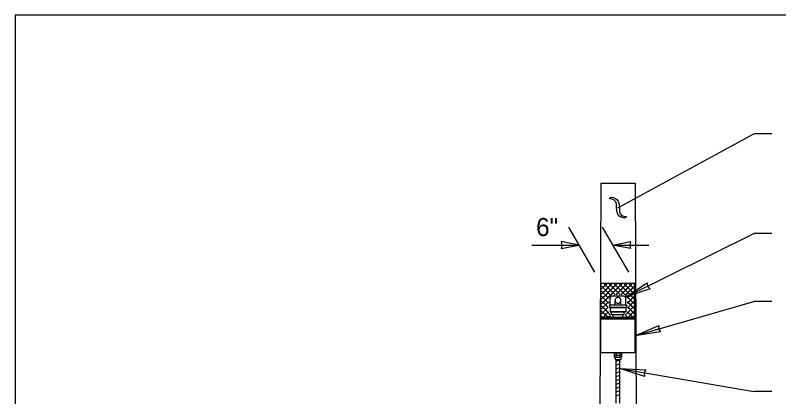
# Model space of a CAD drawing. Extents: x 99862 to 103151, y 100000 to 105076.
# Drawn here: x 99862 to 100537, y 101738 to 102076 of the extents above; entities that cross this region are included whole.
import ezdxf

# ---------------------------------------------------------------- set-up
doc = ezdxf.new("R2010")
doc.units = 0
for name, color, linetype in [('Level 1', 7, 'Continuous'), ('Level 15', 7, 'Continuous'), ('Level 20', 7, 'Continuous'), ('Level 40', 7, 'Continuous')]:
    doc.layers.add(name, color=color, linetype=linetype)

msp = doc.modelspace()

# ---------------------------------------------------------------- linework, layer by layer
at = {"layer": 'Level 1'}
for p, q in [((100379.91, 101927.16), (100378.26, 101563.05)), ((100379.91, 101927.16), (100410.16, 101927.16)), ((100410.16, 101927.16), (100411.8, 101563.05)), ((100410.03, 101838.33), (100380.03, 101838.33)), ((100380.03, 101808.33), (100380.03, 101838.33)), ((100380.84, 101838.33), (100380.03, 101837.52)), ((100383.98, 101837.05), (100382.71, 101838.33)), ((100385.26, 101838.33), (100383.98, 101837.05)), ((100388.4, 101837.05), (100387.13, 101838.33)), ((100389.68, 101838.33), (100388.4, 101837.05)), ((100392.82, 101837.05), (100391.55, 101838.33)), ((100394.1, 101838.33), (100392.82, 101837.05)), ((100397.24, 101837.05), (100395.97, 101838.33)), ((100398.52, 101838.33), (100397.24, 101837.05)), ((100401.66, 101837.05), (100400.39, 101838.33)), ((100402.93, 101838.33), (100401.66, 101837.05)), ((100406.08, 101837.05), (100404.81, 101838.33)), ((100407.35, 101838.33), (100406.08, 101837.05)), ((100410.03, 101837.52), (100409.23, 101838.33)), ((100410.03, 101808.33), (100410.03, 101838.33)), ((100380.03, 101836.59), (100381.77, 101834.84)), ((100381.77, 101834.84), (100380.03, 101833.1)), ((100380.03, 101832.17), (100381.77, 101830.42)), ((100381.77, 101834.84), (100383.98, 101837.05)), ((100383.98, 101832.63), (100381.77, 101834.84)), ((100381.77, 101830.42), (100383.98, 101832.63)), ((100383.98, 101837.05), (100386.19, 101834.84)), ((100386.19, 101834.84), (100383.98, 101832.63)), ((100383.98, 101832.63), (100386.19, 101830.42)), ((100386.19, 101834.84), (100388.4, 101837.05)), ((100388.4, 101832.63), (100386.19, 101834.84)), ((100386.19, 101830.42), (100388.4, 101832.63)), ((100388.4, 101837.05), (100390.61, 101834.84)), ((100390.61, 101834.84), (100388.4, 101832.63)), ((100388.4, 101832.63), (100390.61, 101830.42)), ((100390.61, 101834.84), (100392.82, 101837.05)), ((100392.82, 101832.63), (100390.61, 101834.84)), ((100390.61, 101830.42), (100392.82, 101832.63)), ((100392.82, 101837.05), (100395.03, 101834.84)), ((100395.03, 101834.84), (100392.82, 101832.63)), ((100392.82, 101832.63), (100395.03, 101830.42)), ((100395.03, 101834.84), (100397.24, 101837.05)), ((100397.24, 101832.63), (100395.03, 101834.84)), ((100395.03, 101830.42), (100397.24, 101832.63)), ((100397.24, 101837.05), (100399.45, 101834.84)), ((100399.45, 101834.84), (100397.24, 101832.63)), ((100397.24, 101832.63), (100399.45, 101830.42)), ((100399.45, 101834.84), (100401.66, 101837.05)), ((100401.66, 101832.63), (100399.45, 101834.84)), ((100399.45, 101830.42), (100401.66, 101832.63)), ((100401.66, 101837.05), (100403.87, 101834.84)), ((100403.87, 101834.84), (100401.66, 101832.63)), ((100401.66, 101832.63), (100403.87, 101830.42)), ((100403.87, 101834.84), (100406.08, 101837.05)), ((100406.08, 101832.63), (100403.87, 101834.84)), ((100403.87, 101830.42), (100406.08, 101832.63)), ((100406.08, 101837.05), (100408.29, 101834.84)), ((100408.29, 101834.84), (100406.08, 101832.63)), ((100406.08, 101832.63), (100408.29, 101830.42)), ((100408.29, 101834.84), (100410.03, 101836.58)), ((100410.03, 101833.1), (100408.29, 101834.84)), ((100408.29, 101830.42), (100410.03, 101832.17)), ((100381.77, 101830.42), (100380.03, 101828.68)), ((100380.03, 101827.75), (100381.77, 101826)), ((100381.77, 101826), (100380.03, 101824.26)), ((100383.98, 101828.21), (100381.77, 101830.42)), ((100381.77, 101826), (100383.98, 101828.21)), ((100383.98, 101823.79), (100381.77, 101826)), ((100386.19, 101830.42), (100383.98, 101828.21)), ((100383.98, 101828.21), (100386.19, 101826)), ((100386.19, 101826), (100383.98, 101823.79)), ((100388.4, 101828.21), (100386.19, 101830.42)), ((100386.19, 101826), (100388.4, 101828.21)), ((100386.91, 101825.29), (100386.19, 101826)), ((100388.16, 101819.66), (100388.16, 101825.49)), ((100390.61, 101830.42), (100388.4, 101828.21)), ((100388.4, 101828.21), (100388.51, 101828.1)), ((100400.24, 101827.16), (100389.82, 101827.16)), ((100392.62, 101828.41), (100390.61, 101830.42)), ((100395.03, 101830.42), (100393.02, 101828.41)), ((100397.04, 101828.41), (100395.03, 101830.42)), ((100399.45, 101830.42), (100397.44, 101828.41)), ((100401.66, 101828.21), (100399.45, 101830.42)), ((100401.55, 101828.1), (100401.66, 101828.21)), ((100403.87, 101830.42), (100401.66, 101828.21)), ((100401.66, 101828.21), (100403.87, 101826)), ((100401.91, 101819.66), (100401.91, 101825.49)), ((100403.87, 101826), (100403.16, 101825.29)), ((100406.08, 101828.21), (100403.87, 101830.42)), ((100403.87, 101826), (100406.08, 101828.21)), ((100406.08, 101823.79), (100403.87, 101826)), ((100408.29, 101830.42), (100406.08, 101828.21)), ((100406.08, 101828.21), (100408.29, 101826)), ((100408.29, 101826), (100406.08, 101823.79)), ((100410.03, 101828.68), (100408.29, 101830.42)), ((100408.29, 101826), (100410.03, 101827.75)), ((100410.03, 101824.26), (100408.29, 101826)), ((100380.03, 101823.33), (100381.77, 101821.59)), ((100381.77, 101821.59), (100380.03, 101819.84)), ((100380.03, 101818.91), (100381.77, 101817.17)), ((100381.77, 101821.59), (100383.98, 101823.79)), ((100383.98, 101819.38), (100381.77, 101821.59)), ((100381.77, 101817.17), (100383.98, 101819.38)), ((100383.98, 101823.79), (100386.19, 101821.59)), ((100386.19, 101821.59), (100383.98, 101819.38)), ((100383.98, 101819.38), (100386.19, 101817.17)), ((100386.19, 101821.59), (100386.91, 101822.3)), ((100386.87, 101820.91), (100386.19, 101821.59)), ((100388.16, 101819.66), (100387.53, 101819.66)), ((100387.53, 101819.66), (100387.53, 101817.16)), ((100388.16, 101819.66), (100401.91, 101819.66)), ((100392.53, 101819.66), (100392.53, 101823.49)), ((100397.53, 101819.66), (100397.53, 101823.49)), ((100401.91, 101819.66), (100402.53, 101819.66)), ((100402.53, 101819.66), (100402.53, 101817.16)), ((100403.16, 101822.3), (100403.87, 101821.59)), ((100403.87, 101821.59), (100403.2, 101820.91)), ((100403.87, 101821.59), (100406.08, 101823.79)), ((100406.08, 101819.38), (100403.87, 101821.59)), ((100403.87, 101817.17), (100406.08, 101819.38)), ((100406.08, 101823.79), (100408.29, 101821.59)), ((100408.29, 101821.59), (100406.08, 101819.38)), ((100406.08, 101819.38), (100408.29, 101817.17)), ((100408.29, 101821.59), (100410.03, 101823.33)), ((100410.03, 101819.84), (100408.29, 101821.59)), ((100408.29, 101817.17), (100410.03, 101818.91)), ((100381.77, 101817.17), (100380.03, 101815.42)), ((100380.03, 101814.49), (100381.77, 101812.75)), ((100381.77, 101812.75), (100380.03, 101811)), ((100383.98, 101814.96), (100381.77, 101817.17)), ((100381.77, 101812.75), (100383.98, 101814.96)), ((100383.98, 101810.54), (100381.77, 101812.75)), ((100386.19, 101817.17), (100383.98, 101814.96)), ((100383.98, 101814.96), (100386.19, 101812.75)), ((100386.19, 101812.75), (100383.98, 101810.54)), ((100386.19, 101817.17), (100386.28, 101817.25)), ((100386.28, 101817.08), (100386.19, 101817.17)), ((100386.19, 101812.75), (100386.91, 101813.46)), ((100388.25, 101810.69), (100386.19, 101812.75)), ((100402.53, 101817.16), (100387.53, 101817.16)), ((100388.16, 101817.16), (100401.91, 101817.16)), ((100388.16, 101817.16), (100388.16, 101813.41)), ((100388.16, 101813.72), (100401.91, 101813.72)), ((100388.16, 101813.41), (100401.91, 101813.41)), ((100389.41, 101811.22), (100389.41, 101813.41)), ((100389.72, 101810.91), (100400.34, 101810.91)), ((100390.66, 101808.41), (100390.66, 101810.91)), ((100399.41, 101808.41), (100399.41, 101810.91)), ((100400.66, 101811.22), (100400.66, 101813.41)), ((100403.87, 101812.75), (100401.81, 101810.69)), ((100401.91, 101817.16), (100401.91, 101813.41)), ((100403.16, 101813.46), (100403.87, 101812.75)), ((100403.78, 101817.25), (100403.87, 101817.17)), ((100403.87, 101817.17), (100403.78, 101817.08)), ((100406.08, 101814.96), (100403.87, 101817.17)), ((100403.87, 101812.75), (100406.08, 101814.96)), ((100406.08, 101810.54), (100403.87, 101812.75)), ((100408.29, 101817.17), (100406.08, 101814.96)), ((100406.08, 101814.96), (100408.29, 101812.75)), ((100408.29, 101812.75), (100406.08, 101810.54)), ((100410.03, 101815.42), (100408.29, 101817.17)), ((100408.29, 101812.75), (100410.03, 101814.49)), ((100410.03, 101811), (100408.29, 101812.75)), ((100380.03, 101810.07), (100381.77, 101808.33)), ((100410.03, 101808.33), (100380.03, 101808.33)), ((100380.03, 101807.79), (100380.03, 101808.27)), ((100410.03, 101808.27), (100380.03, 101808.27)), ((100410.03, 101807.79), (100380.03, 101807.79)), ((100380.03, 101807.16), (100410.03, 101807.16)), ((100380.03, 101777.16), (100380.03, 101807.16)), ((100381.77, 101808.33), (100383.98, 101810.54)), ((100383.98, 101810.54), (100386.19, 101808.33)), ((100386.19, 101808.33), (100388.35, 101810.48)), ((100391.91, 101807.16), (100398.16, 101807.16)), ((100401.72, 101810.48), (100403.87, 101808.33)), ((100403.87, 101808.33), (100406.08, 101810.54)), ((100406.08, 101810.54), (100408.29, 101808.33)), ((100408.29, 101808.33), (100410.03, 101810.07)), ((100410.03, 101807.79), (100410.03, 101808.27)), ((100410.03, 101807.16), (100410.03, 101777.16)), ((100410.03, 101777.16), (100380.03, 101777.16)), ((100391.81, 101777.16), (100391.81, 101773.13)), ((100391.81, 101777.16), (100398.26, 101777.16)), ((100393.34, 101777.16), (100393.34, 101773.13)), ((100396.56, 101777.16), (100396.56, 101773.13)), ((100398.26, 101777.16), (100398.26, 101773.13)), ((100391.81, 101775.15), (100398.26, 101775.15)), ((100391.81, 101773.13), (100398.26, 101773.13)), ((100392.53, 101773.13), (100392.53, 101771.19)), ((100392.53, 101771.19), (100397.53, 101771.19)), ((100393.43, 101732.7), (100393.43, 101771.19)), ((100393.43, 101769.73), (100396.63, 101770.9)), ((100396.63, 101732.7), (100396.63, 101771.19)), ((100397.53, 101773.13), (100397.53, 101771.19)), ((100393.43, 101766.34), (100396.63, 101767.5)), ((100393.43, 101762.94), (100396.63, 101764.11)), ((100393.43, 101759.55), (100396.63, 101760.71)), ((100393.43, 101756.15), (100396.63, 101757.32)), ((100393.43, 101752.75), (100396.63, 101753.92)), ((100393.43, 101749.36), (100396.63, 101750.53)), ((100393.43, 101745.96), (100396.63, 101747.13)), ((100393.43, 101742.57), (100396.63, 101743.73)), ((100393.43, 101739.17), (100396.63, 101740.34))]:
    msp.add_line(p, q, dxfattribs=at)
msp.add_lwpolyline([(99862, 99999.5), (103151, 99999.5), (103151, 102075.5), (99862, 102075.5)], close=True, dxfattribs=at)
for centre, radius, start, end in [((100389.82, 101825.49), 1.67, 90, 180), ((100395.03, 101823.49), 2.5, 359.99971, 180), ((100400.24, 101825.49), 1.67, 0, 90), ((100395.03, 101823.49), 2.5, 180, 0.00029), ((100389.72, 101811.22), 0.312, 180, 270), ((100400.34, 101811.22), 0.312, 270, 0), ((100391.91, 101808.41), 1.25, 180, 186.29473), ((100391.91, 101808.41), 1.25, 209.97018, 270), ((100398.16, 101808.41), 1.25, 270, 330.02982), ((100398.16, 101808.41), 1.25, 353.70527, 360)]:
    msp.add_arc(centre, radius, start, end, dxfattribs=at)
at = {"layer": 'Level 15'}
for p, q in [((100395.03, 101905.41), (100515.21, 101970.8)), ((100531.21, 101970.8), (100515.21, 101970.8)), ((100387.31, 101913.57), (100389.16, 101914.58)), ((100389.66, 101913), (100387.31, 101913.57)), ((100389.16, 101914.58), (100391.13, 101914.28)), ((100391.27, 101912.34), (100389.66, 101913)), ((100391.13, 101914.28), (100392.79, 101913.6)), ((100392.34, 101911.5), (100391.27, 101912.34)), ((100392.79, 101913.6), (100394.13, 101912.55)), ((100394.13, 101912.55), (100395.17, 101911.13)), ((100393.14, 101910.43), (100392.34, 101911.5)), ((100393.73, 101908.6), (100393.14, 101910.43)), ((100393.89, 101906.06), (100393.73, 101908.6)), ((100394.05, 101901.97), (100393.89, 101906.06)), ((100395.17, 101911.13), (100396.03, 101908.55)), ((100396.03, 101908.55), (100396.29, 101904.14)), ((100394.88, 101899.65), (100394.05, 101901.97)), ((100395.85, 101898.3), (100394.88, 101899.65)), ((100396.29, 101904.14), (100396.44, 101901.72)), ((100396.44, 101901.72), (100396.93, 101900.31)), ((100396.93, 101900.31), (100397.82, 101899.2)), ((100397.82, 101899.2), (100399.2, 101898.29)), ((100397.13, 101897.31), (100395.85, 101898.3)), ((100398.77, 101896.62), (100397.13, 101897.31)), ((100400.88, 101896.21), (100398.77, 101896.62)), ((100399.2, 101898.29), (100402.74, 101897.22)), ((100402.73, 101897.22), (100400.88, 101896.21)), ((100351.19, 101888.29), (100374.26, 101848.33)), ((100381.19, 101888.29), (100404.26, 101848.33)), ((100401.73, 101826.24), (100515.21, 101882.51)), ((100531.21, 101882.51), (100515.21, 101882.51)), ((100318.97, 101872.29), (100360.42, 101872.29)), ((100390.42, 101872.29), (100422.42, 101872.29)), ((100410.03, 101792.16), (100515.21, 101822.58)), ((100531.21, 101822.58), (100515.21, 101822.58)), ((100396.63, 101763.1), (100515.21, 101742.79)), ((100531.21, 101742.79), (100515.21, 101742.79))]:
    msp.add_line(p, q, dxfattribs=at)
for points in [[(100360.42, 101872.29), (100344.7, 101875.37), (100345.43, 101872.29), (100344.7, 101869.2)], [(100390.42, 101872.29), (100406.15, 101875.37), (100405.42, 101872.29), (100406.15, 101869.2)], [(100401.73, 101826.24), (100420.86, 101839.05), (100421.24, 101835.91), (100423.51, 101833.7)], [(100410.03, 101792.16), (100431.13, 101801.37), (100430.95, 101798.21), (100432.79, 101795.64)], [(100396.63, 101763.1), (100419.64, 101762.19), (100418.09, 101759.43), (100418.63, 101756.31)]]:
    msp.add_lwpolyline(points, close=True, dxfattribs=at)
at = {"layer": 'Level 40'}
for points in [[(100383.24, 101807.29), (100383.24, 101807.16), (100381.84, 101807.16), (100381.84, 101807.29)], [(100383.21, 101807.37), (100383.21, 101807.29), (100381.85, 101807.29), (100381.85, 101807.37)], [(100383.04, 101808.29), (100383.04, 101808.69), (100382.02, 101808.69), (100382.02, 101808.29)], [(100383.04, 101807.37), (100383.04, 101807.79), (100382.02, 101807.79), (100382.02, 101807.37)], [(100406.83, 101807.29), (100406.83, 101807.16), (100408.22, 101807.16), (100408.22, 101807.29)], [(100406.85, 101807.37), (100406.85, 101807.29), (100408.21, 101807.29), (100408.21, 101807.37)], [(100407.02, 101808.29), (100407.02, 101808.69), (100408.04, 101808.69), (100408.04, 101808.29)], [(100407.02, 101807.37), (100407.02, 101807.79), (100408.04, 101807.79), (100408.04, 101807.37)]]:
    msp.add_lwpolyline(points, close=True, dxfattribs=at)

# ---------------------------------------------------------------- texts
at = {"layer": 'Level 20'}
msp.add_text('6"', height=16, rotation=360, dxfattribs=at).set_placement((100322.64, 101880.29))

doc.saveas('drawing.dxf')
